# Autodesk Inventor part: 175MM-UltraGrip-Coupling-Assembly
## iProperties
Created: 2012-05
Part Number: 175MM-UltraGrip-Coupling-Assembly
Document SubType Name: Modeling
Designer: D Cole
Density: 1 g/cm^3
Author: D Cole
